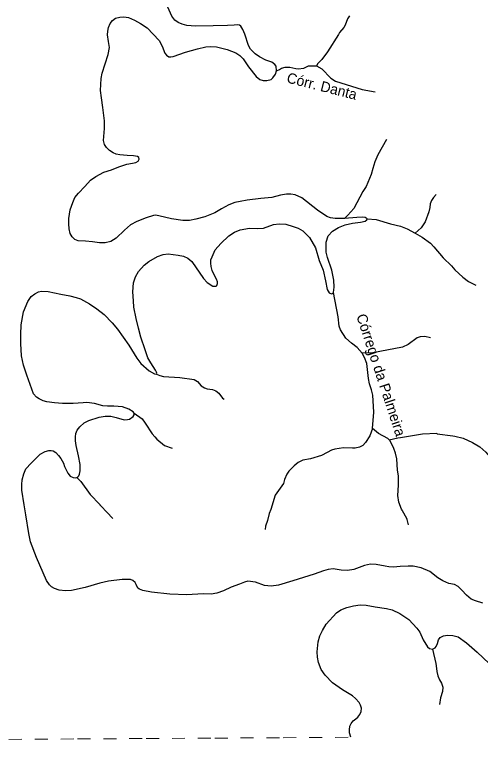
# Model space of a CAD drawing. Extents: x 396 to 422.2, y 7649.8 to 7677.6.
# Drawn here: x 401.58 to 405.17, y 7649.83 to 7655.45 of the extents above; entities that cross this region are included whole.
import ezdxf
from ezdxf.enums import TextEntityAlignment as Align

# ---------------------------------------------------------------- set-up
doc = ezdxf.new("R2010")
doc.units = 0
doc.header["$LTSCALE"] = 0.032
doc.linetypes.add('SHORT_DASHED', pattern=[2.7, 1.5, -1.2])
for name, color, linetype, lineweight in [('2', 7, 'Continuous', 25), ('62', 7, 'SHORT_DASHED', 13), ('7', 7, 'Continuous', 25)]:
    doc.layers.add(name, color=color, linetype=linetype, lineweight=lineweight)
doc.layers.add('61', color=7, linetype='Continuous')

msp = doc.modelspace()

# ---------------------------------------------------------------- linework, layer by layer
at = {"layer": '2'}
for points in [[(403.5977, 7655.0152), (403.593, 7655.0509), (403.5848, 7655.0626), (403.5592, 7655.0812), (403.515, 7655.0975), (403.4649, 7655.1219), (403.4312, 7655.1452), (403.3963, 7655.1825), (403.38, 7655.2092), (403.3509, 7655.2965), (403.3357, 7655.3338), (403.3218, 7655.3594), (403.3101, 7655.3675), (403.295, 7655.3699), (403.2706, 7655.3675), (403.2182, 7655.3629), (403.1065, 7655.3617), (402.9714, 7655.3582), (402.9039, 7655.3652), (402.8678, 7655.3745), (402.8388, 7655.3873), (402.812, 7655.4048), (402.7899, 7655.435), (402.7584, 7655.506)], [(404.1223, 7653.8766), (404.0888, 7653.8754), (404.0492, 7653.8754), (404.0143, 7653.8812), (403.9841, 7653.8917), (403.9131, 7653.9405), (403.7908, 7654.0348), (403.7408, 7654.0569), (403.7059, 7654.0639), (403.6745, 7654.0639), (403.6267, 7654.0546), (403.5592, 7654.0372), (403.4754, 7654.029), (403.3707, 7654.0174), (403.316, 7654.0057), (403.2752, 7653.9987), (403.2298, 7653.9801), (403.1716, 7653.9499), (403.1216, 7653.9196), (403.0436, 7653.8882), (402.9749, 7653.8707), (402.926, 7653.8591), (402.8748, 7653.8591), (402.7875, 7653.873), (402.6886, 7653.8952), (402.6618, 7653.8998), (402.6479, 7653.8975), (402.5897, 7653.88), (402.5175, 7653.8521), (402.4686, 7653.8265), (402.4244, 7653.7857), (402.3592, 7653.7241), (402.3173, 7653.6973), (402.2731, 7653.6868), (402.2312, 7653.6868), (402.1765, 7653.6961), (402.1229, 7653.6996), (402.0659, 7653.7019), (402.0415, 7653.7124), (402.0193, 7653.7334), (402.0054, 7653.7601), (401.9961, 7653.7962), (401.9949, 7653.8346), (401.9949, 7653.8742), (402.0054, 7653.9417), (402.024, 7653.9987), (402.0415, 7654.0372), (402.0682, 7654.0709), (402.1171, 7654.1233), (402.1602, 7654.1698), (402.2021, 7654.2001), (402.2638, 7654.2315), (402.322, 7654.2502), (402.3802, 7654.2734), (402.4407, 7654.2932), (402.4849, 7654.3014), (402.5117, 7654.3072), (402.528, 7654.3188), (402.5361, 7654.3328), (402.5338, 7654.3468), (402.5233, 7654.3537), (402.4931, 7654.3584), (402.4453, 7654.3619), (402.3871, 7654.3654), (402.3604, 7654.3712), (402.3371, 7654.3817), (402.308, 7654.4003), (402.2847, 7654.4236), (402.2696, 7654.4457), (402.2626, 7654.476), (402.2638, 7654.5085), (402.2684, 7654.5691), (402.2696, 7654.6284), (402.2568, 7654.7309), (402.2451, 7654.8065), (402.2393, 7654.8624), (402.244, 7654.9555), (402.251, 7654.9951), (402.2975, 7655.1406), (402.3068, 7655.1941), (402.2999, 7655.2395), (402.2929, 7655.2907), (402.294, 7655.321), (402.301, 7655.3477), (402.3138, 7655.3803), (402.3301, 7655.4013), (402.3534, 7655.4199), (402.3871, 7655.4292), (402.4186, 7655.4304), (402.4547, 7655.4257), (402.5, 7655.4059), (402.5466, 7655.3792), (402.5978, 7655.3466), (402.6444, 7655.2965), (402.6909, 7655.2488)], [(402.6909, 7655.2488), (402.7142, 7655.2034), (402.7352, 7655.1499), (402.7468, 7655.1347), (402.7666, 7655.1231), (402.7806, 7655.1219)], [(402.7806, 7655.1219), (402.7992, 7655.1254), (402.8935, 7655.1592), (402.9866, 7655.1848), (403.0506, 7655.1999), (403.0878, 7655.2011), (403.1344, 7655.1988), (403.2159, 7655.1778), (403.2822, 7655.1522), (403.3136, 7655.1324), (403.3381, 7655.1056), (403.3811, 7655.044), (403.4393, 7654.9695), (403.4684, 7654.9485), (403.494, 7654.9392), (403.522, 7654.9404), (403.5546, 7654.9485), (403.5685, 7654.9602), (403.5883, 7654.9892), (403.5977, 7655.0152)], [(404.0365, 7653.3039), (404.0411, 7653.3458), (404.0388, 7653.3993), (404.0225, 7653.4761), (403.991, 7653.5739), (403.9794, 7653.6158), (403.9794, 7653.6507), (403.9806, 7653.6926), (403.9945, 7653.7404), (404.0294, 7653.7788), (404.0748, 7653.8067), (404.1261, 7653.8276), (404.1819, 7653.8393), (404.2459, 7653.8463), (404.2797, 7653.8556), (404.2937, 7653.8649), (404.2958, 7653.8716)], [(404.2958, 7653.8716), (404.2878, 7653.8777), (404.2809, 7653.8824), (404.2576, 7653.8847), (404.2157, 7653.8824), (404.1223, 7653.8766)], [(402.67, 7652.6754), (402.6729, 7652.6815), (402.6711, 7652.6893), (402.6618, 7652.7068), (402.6269, 7652.7615), (402.6048, 7652.8011), (402.5827, 7652.8628), (402.5501, 7652.9605), (402.5325, 7653.0286), (402.5129, 7653.1048), (402.4966, 7653.191), (402.4919, 7653.241), (402.4884, 7653.3097), (402.4942, 7653.3784), (402.5082, 7653.4261), (402.5315, 7653.4668), (402.5745, 7653.5157), (402.6106, 7653.5425), (402.6781, 7653.5821), (402.7212, 7653.5972), (402.7596, 7653.603), (402.7992, 7653.5984), (402.8364, 7653.5914), (402.8783, 7653.5856), (402.9132, 7653.5704), (402.9423, 7653.5425), (403.0343, 7653.4133), (403.0622, 7653.3807), (403.1053, 7653.3539), (403.1204, 7653.3528), (403.1297, 7653.3539), (403.1367, 7653.3597), (403.1402, 7653.3737), (403.1402, 7653.3877), (403.1344, 7653.4075), (403.1158, 7653.4401), (403.0995, 7653.475), (403.0913, 7653.5041), (403.0902, 7653.5297), (403.0902, 7653.5553), (403.0995, 7653.5809), (403.1227, 7653.6344), (403.167, 7653.6822), (403.2287, 7653.7404), (403.2729, 7653.7695), (403.316, 7653.7881), (403.387, 7653.8009), (403.4521, 7653.7986), (403.4964, 7653.802), (403.5744, 7653.8288), (403.6163, 7653.8346), (403.6675, 7653.8311), (403.7257, 7653.8148), (403.7629, 7653.802), (403.8002, 7653.7799), (403.8514, 7653.7299), (403.8968, 7653.6496), (403.9247, 7653.5506), (403.9561, 7653.4773), (403.9736, 7653.3958), (403.9875, 7653.3283), (404.0027, 7653.3016), (404.0201, 7653.2946), (404.0294, 7653.2969), (404.0365, 7653.3039)], [(402.4977, 7652.3727), (402.4907, 7652.3844), (402.4581, 7652.4053), (402.4069, 7652.4228), (402.3418, 7652.4274), (402.2929, 7652.4274), (402.2556, 7652.4298), (402.1916, 7652.4484), (402.1334, 7652.4554), (402.1043, 7652.4542), (402.0275, 7652.4496), (401.946, 7652.4496), (401.8843, 7652.4531), (401.8238, 7652.4612), (401.7947, 7652.4682), (401.7656, 7652.4845), (401.7435, 7652.4984), (401.7225, 7652.5241), (401.7074, 7652.5578), (401.6702, 7652.666), (401.6434, 7652.7429), (401.6294, 7652.8162), (401.6224, 7652.9105), (401.6236, 7652.9803), (401.6271, 7653.0548), (401.6446, 7653.1549), (401.6772, 7653.234), (401.7039, 7653.2725), (401.7319, 7653.2946), (401.7598, 7653.3085), (401.7842, 7653.3144), (401.8343, 7653.3132), (401.9332, 7653.2922), (402.0007, 7653.2794), (402.0496, 7653.2666), (402.0845, 7653.255), (402.1544, 7653.2166), (402.2091, 7653.1793), (402.2673, 7653.1351), (402.3278, 7653.0711), (402.3685, 7653.0222), (402.457, 7652.8988), (402.5187, 7652.7976), (402.5501, 7652.758), (402.6141, 7652.6998), (402.6549, 7652.6765), (402.67, 7652.6754)], [(402.055, 7651.877), (402.0636, 7651.8839), (402.0706, 7651.8909), (402.0764, 7651.9025), (402.081, 7651.9281), (402.081, 7651.9782), (402.0682, 7652.0445), (402.0496, 7652.1237), (402.045, 7652.1597), (402.045, 7652.1912), (402.0484, 7652.2168), (402.0578, 7652.2424), (402.0799, 7652.2692), (402.1125, 7652.2982), (402.1485, 7652.318), (402.2289, 7652.3425), (402.2754, 7652.3518), (402.3173, 7652.3506), (402.3592, 7652.3413), (402.4197, 7652.3227), (402.4477, 7652.3239), (402.4628, 7652.3285), (402.4896, 7652.3483), (402.4977, 7652.3611), (402.4977, 7652.3727)], [(405.1876, 7650.9074), (405.1329, 7650.9271), (405.0979, 7650.9388), (405.063, 7650.9702), (405.0269, 7651.0098), (404.999, 7651.0366), (404.9699, 7651.0517), (404.9268, 7651.061), (404.8791, 7651.0796), (404.8419, 7651.1029), (404.779, 7651.1529), (404.7127, 7651.1809), (404.651, 7651.1948), (404.6114, 7651.1948), (404.5497, 7651.1902), (404.4997, 7651.1867), (404.4624, 7651.189), (404.4345, 7651.1948), (404.3658, 7651.2076), (404.3216, 7651.2088), (404.2762, 7651.1983), (404.1936, 7651.1692), (404.1435, 7651.1599), (404.0946, 7651.1634), (404.0341, 7651.1727), (403.9957, 7651.1681), (403.9584, 7651.1588), (403.8874, 7651.132), (403.7233, 7651.0796), (403.6116, 7651.0482), (403.5546, 7651.0389), (403.5045, 7651.0459), (403.4347, 7651.0703), (403.3765, 7651.0773), (403.3486, 7651.0715), (403.3113, 7651.0552), (403.2473, 7651.0319), (403.1868, 7651.004), (403.1367, 7650.9853), (403.0913, 7650.9784), (403.0296, 7650.9807), (402.9039, 7650.9737), (402.7724, 7650.9784), (402.6316, 7650.9946), (402.5641, 7651.0051), (402.5396, 7651.0156), (402.5268, 7651.0249), (402.514, 7651.0528), (402.5047, 7651.0691), (402.4884, 7651.0831), (402.4698, 7651.0901), (402.4477, 7651.0901), (402.4046, 7651.0901), (402.2999, 7651.0773), (402.2323, 7651.0633), (402.1206, 7651.0296), (402.0147, 7651.0063), (401.967, 7651.004), (401.9192, 7651.0086), (401.8843, 7651.0214), (401.8599, 7651.0342), (401.8436, 7651.0505), (401.8226, 7651.0843), (401.7435, 7651.26), (401.6993, 7651.3811), (401.6841, 7651.4463), (401.662, 7651.5906), (401.6492, 7651.6674), (401.6318, 7651.7791), (401.6306, 7651.8234), (401.6329, 7651.8594), (401.6457, 7651.9048), (401.6609, 7651.9444), (401.7028, 7651.9886), (401.7738, 7652.0573), (401.811, 7652.0783), (401.8401, 7652.0852)], [(401.8401, 7652.0852), (401.8564, 7652.0852), (401.8739, 7652.0829), (401.8936, 7652.0713), (401.9134, 7652.0485), (401.9326, 7652.0243)], [(401.9326, 7652.0243), (401.9523, 7651.9886), (401.9613, 7651.9625), (401.9855, 7651.9121), (402.0052, 7651.8892), (402.0282, 7651.8777), (402.0441, 7651.8745), (402.055, 7651.877)], [(404.1702, 7649.8738), (404.1609, 7649.9079), (404.1593, 7649.9304), (404.1634, 7649.9605), (404.1726, 7649.9797), (404.1893, 7650.0022), (404.2085, 7650.0172), (404.2252, 7650.0298), (404.2394, 7650.049), (404.2494, 7650.0723), (404.2519, 7650.0982), (404.2457, 7650.1218), (404.2331, 7650.1431), (404.206, 7650.1741), (404.1818, 7650.1944), (404.1062, 7650.2399), (404.0297, 7650.2942), (403.9716, 7650.3523), (403.9406, 7650.3969), (403.9202, 7650.4501), (403.9135, 7650.4928), (403.9106, 7650.5325), (403.9173, 7650.6109), (403.9309, 7650.6555), (403.9522, 7650.6981), (403.9793, 7650.7466), (404.0607, 7650.8347), (404.0936, 7650.857), (404.1382, 7650.8744), (404.1905, 7650.889), (404.2428, 7650.8948), (404.2883, 7650.8928), (404.3581, 7650.8812), (404.4443, 7650.8686), (404.4898, 7650.858), (404.548, 7650.8299), (404.6167, 7650.7824), (404.6797, 7650.7165), (404.7029, 7650.6836), (404.7291, 7650.6264), (404.762, 7650.5712), (404.7766, 7650.5586), (404.8001, 7650.5548)], [(404.8001, 7650.5548), (404.8211, 7650.5644), (404.8298, 7650.5741), (404.8376, 7650.5974), (404.8453, 7650.6245), (404.8599, 7650.6439), (404.8851, 7650.6555), (404.9151, 7650.6613), (404.9567, 7650.6603), (404.9994, 7650.6478), (405.0614, 7650.6032), (405.1437, 7650.5315), (405.2367, 7650.4443)]]:
    msp.add_lwpolyline(points, dxfattribs=at)
at = {"layer": '62'}
msp.add_lwpolyline([(396.4167, 7649.8267), (396.7664, 7649.8289), (397.2959, 7649.8322), (397.8253, 7649.8355), (398.3548, 7649.8388), (398.8842, 7649.842), (399.4136, 7649.8453), (399.9431, 7649.8485), (400.4725, 7649.8518), (401.002, 7649.855), (401.5314, 7649.8581), (402.0608, 7649.8613), (402.5903, 7649.8645), (403.1197, 7649.8676), (403.6491, 7649.8707), (404.1702, 7649.8738)], dxfattribs=at)
at = {"layer": '7'}
for points in [[(404.1589, 7655.4377), (404.1452, 7655.4145), (404.1262, 7655.367), (404.115, 7655.3489), (404.0833, 7655.3097), (404.0761, 7655.2944), (403.9899, 7655.1596), (403.9453, 7655.1014), (403.9167, 7655.0711), (403.9051, 7655.0519)], [(403.5977, 7655.0152), (403.6193, 7655.0236), (403.6362, 7655.0347), (403.6625, 7655.0422), (403.6681, 7655.0438), (403.6939, 7655.0436), (403.6994, 7655.0435), (403.7451, 7655.0312), (403.7647, 7655.0302), (403.8083, 7655.0357), (403.8435, 7655.0519), (403.9051, 7655.0519)], [(403.9051, 7655.0519), (403.9474, 7655.0285), (404.0146, 7654.9589), (404.0519, 7654.9349), (404.2565, 7654.8715), (404.3582, 7654.8532)], [(404.4452, 7654.4839), (404.3787, 7654.3664), (404.3548, 7654.3121), (404.3387, 7654.2616), (404.3277, 7654.2148), (404.2887, 7654.121), (404.2631, 7654.0824), (404.192, 7653.9533), (404.1468, 7653.9008), (404.1223, 7653.8766)], [(404.8287, 7654.0597), (404.8069, 7654.0378), (404.7925, 7654.0153), (404.7833, 7653.9883), (404.78, 7653.9599), (404.772, 7653.928), (404.7443, 7653.8485), (404.712, 7653.8041), (404.6656, 7653.7625)], [(404.2958, 7653.8716), (404.3645, 7653.8668), (404.4751, 7653.8347), (404.5527, 7653.8169), (404.6058, 7653.7958), (404.6656, 7653.7625)], [(404.6656, 7653.7625), (404.7206, 7653.7318), (404.7839, 7653.6848), (404.8101, 7653.6578), (404.8815, 7653.5713), (404.9465, 7653.5096), (404.9728, 7653.4801), (405.0347, 7653.4236), (405.0773, 7653.3906), (405.135, 7653.361)], [(404.2574, 7652.8364), (404.2196, 7652.8807), (404.1758, 7652.9133), (404.1319, 7652.9524), (404.0896, 7653.0169), (404.0799, 7653.046), (404.0734, 7653.1181), (404.0365, 7653.3039)], [(404.7857, 7652.9551), (404.7405, 7652.9646), (404.7059, 7652.9629), (404.6831, 7652.9555), (404.6133, 7652.9041), (404.5679, 7652.884), (404.341, 7652.8388), (404.2574, 7652.8364)], [(404.338, 7652.2548), (404.3469, 7652.381), (404.3398, 7652.5116), (404.3303, 7652.5544), (404.3139, 7652.5991), (404.3057, 7652.6405), (404.2934, 7652.7576), (404.276, 7652.8035), (404.2574, 7652.8364)], [(402.67, 7652.6754), (402.6959, 7652.6638), (402.7248, 7652.6555), (402.8498, 7652.6489), (402.9604, 7652.6335), (402.9859, 7652.6175), (403.0164, 7652.5854), (403.0402, 7652.5689), (403.061, 7652.5623), (403.1034, 7652.5556), (403.1287, 7652.545), (403.1512, 7652.5272), (403.1798, 7652.4907), (403.1923, 7652.4814)], [(402.4977, 7652.3727), (402.5587, 7652.3301), (402.5839, 7652.296), (402.6358, 7652.2141), (402.6578, 7652.1926), (402.6718, 7652.1739), (402.7317, 7652.1243), (402.7903, 7652.1034)], [(404.338, 7652.2548), (404.3168, 7652.1993), (404.2836, 7652.1467), (404.2615, 7652.1257), (404.2374, 7652.1119), (404.2039, 7652.1041), (404.182, 7652.1047), (404.1133, 7652.1065), (404.0473, 7652.0971), (404.0219, 7652.0875), (403.9879, 7652.0697), (403.9435, 7652.0465), (403.8578, 7652.0219), (403.8004, 7652.0123), (403.7626, 7651.9936), (403.7325, 7651.9682), (403.691, 7651.9256), (403.6769, 7651.9041), (403.659, 7651.8632), (403.6493, 7651.8309), (403.5869, 7651.7409), (403.5517, 7651.6309), (403.5388, 7651.6012), (403.5271, 7651.545), (403.5127, 7651.5013), (403.5089, 7651.4758)], [(404.4661, 7652.167), (404.4545, 7652.1779), (404.3847, 7652.218), (404.338, 7652.2548)], [(404.4661, 7652.167), (404.5329, 7652.1834), (404.5532, 7652.1866), (404.7226, 7652.2136), (404.8333, 7652.2205), (404.8366, 7652.2157), (404.9564, 7652.1982), (404.9738, 7652.1957), (405.0372, 7652.1805), (405.1085, 7652.1476), (405.1646, 7652.1142), (405.2116, 7652.0744), (405.2764, 7651.9954), (405.3081, 7651.9387), (405.3286, 7651.8946), (405.3478, 7651.8656), (405.367, 7651.8223), (405.3764, 7651.7771), (405.3797, 7651.7452), (405.3797, 7651.7387), (405.3798, 7651.6522), (405.3623, 7651.5061)], [(404.6159, 7651.5136), (404.6044, 7651.5526), (404.6019, 7651.5611), (404.5697, 7651.6219), (404.5661, 7651.6267), (404.5604, 7651.6342), (404.5408, 7651.6867), (404.5329, 7651.7377), (404.5375, 7651.8191), (404.5375, 7651.8912), (404.5296, 7651.9346), (404.5247, 7652.0211), (404.5149, 7652.0646), (404.5024, 7652.102), (404.4738, 7652.1597), (404.4661, 7652.167)], [(402.055, 7651.877), (402.0863, 7651.8463), (402.1594, 7651.747), (402.2322, 7651.67), (402.2335, 7651.6659), (402.2446, 7651.6578), (402.2873, 7651.6113), (402.3326, 7651.5619)], [(404.8001, 7650.5548), (404.8261, 7650.4436), (404.8302, 7650.4051), (404.8327, 7650.3823), (404.8419, 7650.3468), (404.8539, 7650.3183), (404.8709, 7650.2914), (404.8805, 7650.2608), (404.8773, 7650.2273), (404.8616, 7650.1777), (404.8551, 7650.128)]]:
    msp.add_lwpolyline(points, dxfattribs=at)

# ---------------------------------------------------------------- texts
at = {"layer": '61'}
for s, rotation, p in [('Córr. Danta', 345.87, (403.9378, 7654.8578)), ('Córrego da Palmeira', 288.215, (404.3654, 7652.6559))]:
    msp.add_text(s, height=0.08, rotation=rotation, dxfattribs=at).set_placement(p, align=Align.CENTER)

doc.saveas('drawing.dxf')
